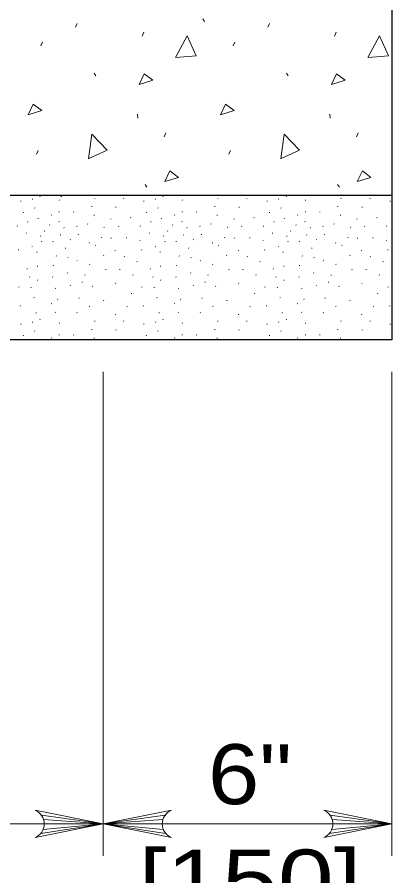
# Model space of a CAD drawing. Extents: x 1083.1 to 1117.1, y 719.4 to 763.4.
# Drawn here: x 1096.472 to 1097.446, y 726.507 to 728.741 of the extents above; entities that cross this region are included whole.
import ezdxf
from ezdxf.enums import TextEntityAlignment as Align

# ---------------------------------------------------------------- set-up
doc = ezdxf.new("R2010")
doc.units = 0
doc.header["$LTSCALE"] = 0.062
doc.layers.add('1', color=7, linetype='Continuous', lineweight=13)

msp = doc.modelspace()

# ---------------------------------------------------------------- linework, layer by layer
at = {"layer": '1'}
for p, q in [((1096.62383, 728.71467), (1096.62825, 728.72467)), ((1096.95492, 728.73642), (1096.95933, 728.72975)), ((1097.12383, 728.71467), (1097.12825, 728.72467)), ((1096.797, 728.6915), (1096.80142, 728.7015)), ((1097.297, 728.6915), (1097.30142, 728.7015)), ((1096.53392, 728.66592), (1096.53833, 728.67592)), ((1097.03392, 728.66592), (1097.03833, 728.67592)), ((1096.67267, 728.59492), (1096.67708, 728.58825)), ((1097.17267, 728.59492), (1097.17708, 728.58825)), ((1096.78483, 728.4885), (1096.786, 728.4785)), ((1097.28483, 728.4885), (1097.286, 728.4785)), ((1096.85408, 728.42958), (1096.8585, 728.43958)), ((1097.35408, 728.42958), (1097.3585, 728.43958)), ((1096.52275, 728.38408), (1096.52725, 728.39408)), ((1097.02275, 728.38408), (1097.02725, 728.39408)), ((1096.80533, 728.30533), (1096.80983, 728.29867)), ((1097.30533, 728.30533), (1097.30983, 728.29867)), ((1096.53142, 728.27367), (1096.532, 728.27533)), ((1096.58583, 728.2755), (1096.5875, 728.27383)), ((1096.85142, 728.27367), (1096.852, 728.27533)), ((1096.95492, 728.27708), (1096.95525, 728.27658)), ((1097.17142, 728.27367), (1097.172, 728.27533)), ((1096.48267, 728.26242), (1096.481, 728.26208)), ((1096.512, 728.26642), (1096.51258, 728.26808)), ((1096.5815, 728.26408), (1096.58208, 728.26575)), ((1096.67383, 728.26875), (1096.67433, 728.27042)), ((1096.749, 728.26875), (1096.74958, 728.27042)), ((1096.80267, 728.26242), (1096.801, 728.26208)), ((1096.832, 728.26642), (1096.83258, 728.26808)), ((1096.9015, 728.26408), (1096.90208, 728.26575)), ((1096.99383, 728.26875), (1096.99433, 728.27042)), ((1097.069, 728.26875), (1097.06958, 728.27042)), ((1097.12267, 728.26242), (1097.121, 728.26208)), ((1097.152, 728.26642), (1097.15258, 728.26808)), ((1097.2215, 728.26408), (1097.22208, 728.26575)), ((1097.31383, 728.26875), (1097.31433, 728.27042)), ((1097.389, 728.26875), (1097.38958, 728.27042)), ((1097.44267, 728.26242), (1097.441, 728.26208)), ((1096.488, 728.23158), (1096.4885, 728.23325)), ((1096.51867, 728.24367), (1096.51783, 728.2445)), ((1096.5825, 728.23458), (1096.58075, 728.23425)), ((1096.61875, 728.23317), (1096.61933, 728.23483)), ((1096.667, 728.2485), (1096.66525, 728.24817)), ((1096.72983, 728.247), (1096.72808, 728.24658)), ((1096.808, 728.23158), (1096.8085, 728.23325)), ((1096.83867, 728.24367), (1096.83783, 728.2445)), ((1096.9025, 728.23458), (1096.90075, 728.23425)), ((1096.93875, 728.23317), (1096.93933, 728.23483)), ((1096.987, 728.2485), (1096.98525, 728.24817)), ((1097.04983, 728.247), (1097.04808, 728.24658)), ((1097.128, 728.23158), (1097.1285, 728.23325)), ((1097.15867, 728.24367), (1097.15783, 728.2445)), ((1097.2225, 728.23458), (1097.22075, 728.23425)), ((1097.25875, 728.23317), (1097.25933, 728.23483)), ((1097.307, 728.2485), (1097.30525, 728.24817)), ((1097.36983, 728.247), (1097.36808, 728.24658)), ((1096.49958, 728.20767), (1096.50017, 728.20933)), ((1096.52675, 728.21642), (1096.52733, 728.21808)), ((1096.56208, 728.22558), (1096.56125, 728.22633)), ((1096.58125, 728.20808), (1096.58042, 728.20892)), ((1096.67317, 728.22608), (1096.6715, 728.22575)), ((1096.71625, 728.21558), (1096.71542, 728.21642)), ((1096.76817, 728.21892), (1096.76733, 728.21975)), ((1096.81958, 728.20767), (1096.82017, 728.20933)), ((1096.84675, 728.21642), (1096.84733, 728.21808)), ((1096.88208, 728.22558), (1096.88125, 728.22633)), ((1096.90125, 728.20808), (1096.90042, 728.20892)), ((1096.99317, 728.22608), (1096.9915, 728.22575)), ((1097.03625, 728.21558), (1097.03542, 728.21642)), ((1097.08817, 728.21892), (1097.08733, 728.21975)), ((1097.13958, 728.20767), (1097.14017, 728.20933)), ((1097.16675, 728.21642), (1097.16733, 728.21808)), ((1097.20208, 728.22558), (1097.20125, 728.22633)), ((1097.22125, 728.20808), (1097.22042, 728.20892)), ((1097.31317, 728.22608), (1097.3115, 728.22575)), ((1097.35625, 728.21558), (1097.35542, 728.21642)), ((1097.40817, 728.21892), (1097.40733, 728.21975)), ((1096.4725, 728.196), (1096.473, 728.19767)), ((1096.55708, 728.19975), (1096.55625, 728.20058)), ((1096.59458, 728.19308), (1096.59375, 728.19392)), ((1096.62792, 728.19642), (1096.62708, 728.19725)), ((1096.65625, 728.20225), (1096.65542, 728.20308)), ((1096.69958, 728.19475), (1096.69792, 728.19392)), ((1096.73625, 728.19642), (1096.73542, 728.19725)), ((1096.7925, 728.196), (1096.793, 728.19767)), ((1096.87708, 728.19975), (1096.87625, 728.20058)), ((1096.91458, 728.19308), (1096.91375, 728.19392)), ((1096.94792, 728.19642), (1096.94708, 728.19725)), ((1096.97625, 728.20225), (1096.97542, 728.20308)), ((1097.01958, 728.19475), (1097.01792, 728.19392)), ((1097.05625, 728.19642), (1097.05542, 728.19725)), ((1097.1125, 728.196), (1097.113, 728.19767)), ((1097.19708, 728.19975), (1097.19625, 728.20058)), ((1097.23458, 728.19308), (1097.23375, 728.19392)), ((1097.26792, 728.19642), (1097.26708, 728.19725)), ((1097.29625, 728.20225), (1097.29542, 728.20308)), ((1097.33958, 728.19475), (1097.33792, 728.19392)), ((1097.37625, 728.19642), (1097.37542, 728.19725)), ((1097.4325, 728.196), (1097.433, 728.19767)), ((1096.49575, 728.178), (1096.49633, 728.17967)), ((1096.533, 728.17033), (1096.5335, 728.172)), ((1096.54308, 728.18475), (1096.54375, 728.18442)), ((1096.54375, 728.18442), (1096.54408, 728.184)), ((1096.58467, 728.17342), (1096.58525, 728.17508)), ((1096.63117, 728.17492), (1096.63175, 728.17658)), ((1096.69167, 728.16717), (1096.69225, 728.16883)), ((1096.7165, 728.16542), (1096.717, 728.16708)), ((1096.75775, 728.16683), (1096.756, 728.16642)), ((1096.81575, 728.178), (1096.81633, 728.17967)), ((1096.853, 728.17033), (1096.8535, 728.172)), ((1096.86308, 728.18475), (1096.86375, 728.18442)), ((1096.86375, 728.18442), (1096.86408, 728.184)), ((1096.90467, 728.17342), (1096.90525, 728.17508)), ((1096.95117, 728.17492), (1096.95175, 728.17658)), ((1097.01167, 728.16717), (1097.01225, 728.16883)), ((1097.0365, 728.16542), (1097.037, 728.16708)), ((1097.07775, 728.16683), (1097.076, 728.16642)), ((1097.13575, 728.178), (1097.13633, 728.17967)), ((1097.173, 728.17033), (1097.1735, 728.172)), ((1097.18308, 728.18475), (1097.18375, 728.18442)), ((1097.18375, 728.18442), (1097.18408, 728.184)), ((1097.22467, 728.17342), (1097.22525, 728.17508)), ((1097.27117, 728.17492), (1097.27175, 728.17658)), ((1097.33167, 728.16717), (1097.33225, 728.16883)), ((1097.3565, 728.16542), (1097.357, 728.16708)), ((1097.39775, 728.16683), (1097.396, 728.16642)), ((1096.51125, 728.143), (1096.51183, 728.14458)), ((1096.53608, 728.15633), (1096.53667, 728.158)), ((1096.56525, 728.15608), (1096.56583, 728.15775)), ((1096.61075, 728.162), (1096.60992, 728.16283)), ((1096.65983, 728.153), (1096.66042, 728.15467)), ((1096.67667, 728.1465), (1096.67583, 728.14733)), ((1096.79217, 728.15967), (1096.79133, 728.1605)), ((1096.83125, 728.143), (1096.83183, 728.14458)), ((1096.85608, 728.15633), (1096.85667, 728.158)), ((1096.88525, 728.15608), (1096.88583, 728.15775)), ((1096.93075, 728.162), (1096.92992, 728.16283)), ((1096.97983, 728.153), (1096.98042, 728.15467)), ((1096.99667, 728.1465), (1096.99583, 728.14733)), ((1097.11217, 728.15967), (1097.11133, 728.1605)), ((1097.15125, 728.143), (1097.15183, 728.14458)), ((1097.17608, 728.15633), (1097.17667, 728.158)), ((1097.20525, 728.15608), (1097.20583, 728.15775)), ((1097.25075, 728.162), (1097.24992, 728.16283)), ((1097.29983, 728.153), (1097.30042, 728.15467)), ((1097.31667, 728.1465), (1097.31583, 728.14733)), ((1097.43217, 728.15967), (1097.43133, 728.1605)), ((1096.47558, 728.13442), (1096.47617, 728.13608)), ((1096.52458, 728.12967), (1096.52283, 728.12933)), ((1096.57425, 728.11942), (1096.57342, 728.12025)), ((1096.59783, 728.13908), (1096.59842, 728.14075)), ((1096.69758, 728.121), (1096.69675, 728.12183)), ((1096.72825, 728.13358), (1096.7265, 728.13317)), ((1096.79558, 728.13442), (1096.79617, 728.13608)), ((1096.84458, 728.12967), (1096.84283, 728.12933)), ((1096.89425, 728.11942), (1096.89342, 728.12025)), ((1096.91783, 728.13908), (1096.91842, 728.14075)), ((1097.01758, 728.121), (1097.01675, 728.12183)), ((1097.04825, 728.13358), (1097.0465, 728.13317)), ((1097.11558, 728.13442), (1097.11617, 728.13608)), ((1097.16458, 728.12967), (1097.16283, 728.12933)), ((1097.21425, 728.11942), (1097.21342, 728.12025)), ((1097.23783, 728.13908), (1097.23842, 728.14075)), ((1097.33758, 728.121), (1097.33675, 728.12183)), ((1097.36825, 728.13358), (1097.3665, 728.13317)), ((1097.43558, 728.13442), (1097.43617, 728.13608)), ((1096.6045, 728.11475), (1096.60367, 728.11558)), ((1096.62808, 728.10658), (1096.62858, 728.10825)), ((1096.66108, 728.09775), (1096.66025, 728.09858)), ((1096.75108, 728.11708), (1096.75025, 728.11792)), ((1096.78483, 728.10492), (1096.78317, 728.10458)), ((1096.9245, 728.11475), (1096.92367, 728.11558)), ((1096.94808, 728.10658), (1096.94858, 728.10825)), ((1096.98108, 728.09775), (1096.98025, 728.09858)), ((1097.07108, 728.11708), (1097.07025, 728.11792)), ((1097.10483, 728.10492), (1097.10317, 728.10458)), ((1097.2445, 728.11475), (1097.24367, 728.11558)), ((1097.26808, 728.10658), (1097.26858, 728.10825)), ((1097.30108, 728.09775), (1097.30025, 728.09858)), ((1097.39108, 728.11708), (1097.39025, 728.11792)), ((1097.42483, 728.10492), (1097.42317, 728.10458)), ((1096.49808, 728.08567), (1096.49858, 728.08733)), ((1096.52617, 728.09333), (1096.52442, 728.09292)), ((1096.566, 728.09425), (1096.56658, 728.09592)), ((1096.60375, 728.07458), (1096.60292, 728.07542)), ((1096.7025, 728.08342), (1096.70308, 728.08508)), ((1096.73992, 728.08483), (1096.73817, 728.08442)), ((1096.81808, 728.08567), (1096.81858, 728.08733)), ((1096.84617, 728.09333), (1096.84442, 728.09292)), ((1096.886, 728.09425), (1096.88658, 728.09592)), ((1096.92375, 728.07458), (1096.92292, 728.07542)), ((1097.0225, 728.08342), (1097.02308, 728.08508)), ((1097.05992, 728.08483), (1097.05817, 728.08442)), ((1097.13808, 728.08567), (1097.13858, 728.08733)), ((1097.16617, 728.09333), (1097.16442, 728.09292)), ((1097.206, 728.09425), (1097.20658, 728.09592)), ((1097.24375, 728.07458), (1097.24292, 728.07542)), ((1097.3425, 728.08342), (1097.34308, 728.08508)), ((1097.37992, 728.08483), (1097.37817, 728.08442)), ((1096.5055, 728.0645), (1096.50467, 728.06533)), ((1096.52525, 728.05575), (1096.52575, 728.05742)), ((1096.56542, 728.06433), (1096.56458, 728.06517)), ((1096.64217, 728.05158), (1096.6405, 728.05117)), ((1096.64825, 728.06867), (1096.64875, 728.07033)), ((1096.77308, 728.06942), (1096.77367, 728.07108)), ((1096.8255, 728.0645), (1096.82467, 728.06533)), ((1096.84525, 728.05575), (1096.84575, 728.05742)), ((1096.88542, 728.06433), (1096.88458, 728.06517)), ((1096.96217, 728.05158), (1096.9605, 728.05117)), ((1096.96825, 728.06867), (1096.96875, 728.07033)), ((1097.09308, 728.06942), (1097.09367, 728.07108)), ((1097.1455, 728.0645), (1097.14467, 728.06533)), ((1097.16525, 728.05575), (1097.16575, 728.05742)), ((1097.20542, 728.06433), (1097.20458, 728.06517)), ((1097.28217, 728.05158), (1097.2805, 728.05117)), ((1097.28825, 728.06867), (1097.28875, 728.07033)), ((1097.41308, 728.06942), (1097.41367, 728.07108)), ((1096.47725, 728.03917), (1096.47558, 728.03883)), ((1096.50817, 728.037), (1096.50867, 728.03867)), ((1096.57292, 728.03608), (1096.57125, 728.03525)), ((1096.61075, 728.04283), (1096.60992, 728.04367)), ((1096.66883, 728.0405), (1096.668, 728.04133)), ((1096.72858, 728.04825), (1096.72775, 728.04908)), ((1096.79725, 728.03917), (1096.79558, 728.03883)), ((1096.82817, 728.037), (1096.82867, 728.03867)), ((1096.89292, 728.03608), (1096.89125, 728.03525)), ((1096.93075, 728.04283), (1096.92992, 728.04367)), ((1096.98883, 728.0405), (1096.988, 728.04133)), ((1097.04858, 728.04825), (1097.04775, 728.04908)), ((1097.11725, 728.03917), (1097.11558, 728.03883)), ((1097.14817, 728.037), (1097.14867, 728.03867)), ((1097.21292, 728.03608), (1097.21125, 728.03525)), ((1097.25075, 728.04283), (1097.24992, 728.04367)), ((1097.30883, 728.0405), (1097.308, 728.04133)), ((1097.36858, 728.04825), (1097.36775, 728.04908)), ((1097.43725, 728.03917), (1097.43558, 728.03883)), ((1096.51633, 728.01033), (1096.5155, 728.01117)), ((1096.57792, 728.00617), (1096.57708, 728.007)), ((1096.63275, 728.00908), (1096.63325, 728.01075)), ((1096.76917, 728.0215), (1096.76975, 728.02317)), ((1096.83633, 728.01033), (1096.8355, 728.01117)), ((1096.89792, 728.00617), (1096.89708, 728.007)), ((1096.95275, 728.00908), (1096.95325, 728.01075)), ((1097.08917, 728.0215), (1097.08975, 728.02317)), ((1097.15633, 728.01033), (1097.1555, 728.01117)), ((1097.21792, 728.00617), (1097.21708, 728.007)), ((1097.27275, 728.00908), (1097.27325, 728.01075)), ((1097.40917, 728.0215), (1097.40975, 728.02317)), ((1096.48025, 727.989), (1096.48075, 727.99067)), ((1096.56208, 727.99617), (1096.56042, 727.99533)), ((1096.66158, 727.98892), (1096.65983, 727.9885)), ((1096.69708, 728.00292), (1096.69767, 728.00458)), ((1096.75808, 727.98708), (1096.75725, 727.98792)), ((1096.80025, 727.989), (1096.80075, 727.99067)), ((1096.88208, 727.99617), (1096.88042, 727.99533)), ((1096.98158, 727.98892), (1096.97983, 727.9885)), ((1097.01708, 728.00292), (1097.01767, 728.00458)), ((1097.07808, 727.98708), (1097.07725, 727.98792)), ((1097.12025, 727.989), (1097.12075, 727.99067)), ((1097.20208, 727.99617), (1097.20042, 727.99533)), ((1097.30158, 727.98892), (1097.29983, 727.9885)), ((1097.33708, 728.00292), (1097.33767, 728.00458)), ((1097.39808, 727.98708), (1097.39725, 727.98792)), ((1097.44025, 727.989), (1097.44075, 727.99067)), ((1096.52225, 727.97183), (1096.5205, 727.9715)), ((1096.57208, 727.97292), (1096.57125, 727.97375)), ((1096.62858, 727.97175), (1096.62775, 727.9725)), ((1096.72733, 727.96667), (1096.72792, 727.96833)), ((1096.84225, 727.97183), (1096.8405, 727.9715)), ((1096.89208, 727.97292), (1096.89125, 727.97375)), ((1096.94858, 727.97175), (1096.94775, 727.9725)), ((1097.04733, 727.96667), (1097.04792, 727.96833)), ((1097.16225, 727.97183), (1097.1605, 727.9715)), ((1097.21208, 727.97292), (1097.21125, 727.97375)), ((1097.26858, 727.97175), (1097.26775, 727.9725)), ((1097.36733, 727.96667), (1097.36792, 727.96833)), ((1096.48267, 727.9425), (1096.481, 727.94217)), ((1096.512, 727.9465), (1096.51258, 727.94817)), ((1096.53142, 727.95375), (1096.532, 727.95542)), ((1096.5815, 727.94417), (1096.58208, 727.94583)), ((1096.67383, 727.94883), (1096.67433, 727.9505)), ((1096.749, 727.94883), (1096.74958, 727.9505)), ((1096.80267, 727.9425), (1096.801, 727.94217)), ((1096.832, 727.9465), (1096.83258, 727.94817)), ((1096.85142, 727.95375), (1096.852, 727.95542)), ((1096.9015, 727.94417), (1096.90208, 727.94583)), ((1096.99383, 727.94883), (1096.99433, 727.9505)), ((1097.069, 727.94883), (1097.06958, 727.9505)), ((1097.12267, 727.9425), (1097.121, 727.94217)), ((1097.152, 727.9465), (1097.15258, 727.94817)), ((1097.17142, 727.95375), (1097.172, 727.95542)), ((1097.2215, 727.94417), (1097.22208, 727.94583)), ((1097.31383, 727.94883), (1097.31433, 727.9505)), ((1097.389, 727.94883), (1097.38958, 727.9505)), ((1097.44267, 727.9425), (1097.441, 727.94217)), ((1096.51867, 727.92375), (1096.51783, 727.92458)), ((1096.667, 727.92858), (1096.66525, 727.92825)), ((1096.72983, 727.92708), (1096.72808, 727.92667)), ((1096.83867, 727.92375), (1096.83783, 727.92458)), ((1096.987, 727.92858), (1096.98525, 727.92825)), ((1097.04983, 727.92708), (1097.04808, 727.92667)), ((1097.15867, 727.92375), (1097.15783, 727.92458)), ((1097.307, 727.92858), (1097.30525, 727.92825)), ((1097.36983, 727.92708), (1097.36808, 727.92667)), ((1096.488, 727.91167), (1096.4885, 727.91333)), ((1096.56208, 727.90567), (1096.56125, 727.90642)), ((1096.5825, 727.91467), (1096.58075, 727.91433)), ((1096.61875, 727.91325), (1096.61933, 727.91492)), ((1096.67317, 727.90617), (1096.6715, 727.90583)), ((1096.808, 727.91167), (1096.8085, 727.91333)), ((1096.88208, 727.90567), (1096.88125, 727.90642)), ((1096.9025, 727.91467), (1096.90075, 727.91433)), ((1096.93875, 727.91325), (1096.93933, 727.91492)), ((1096.99317, 727.90617), (1096.9915, 727.90583)), ((1097.128, 727.91167), (1097.1285, 727.91333)), ((1097.20208, 727.90567), (1097.20125, 727.90642)), ((1097.2225, 727.91467), (1097.22075, 727.91433)), ((1097.25875, 727.91325), (1097.25933, 727.91492)), ((1097.31317, 727.90617), (1097.3115, 727.90583)), ((1096.69608, 727.81825), (1096.69608, 726.55892)), ((1097.44608, 727.81825), (1097.44608, 726.55892)), ((1096.53583, 726.66467), (1096.69608, 726.64225)), ((1096.54125, 726.65358), (1096.69608, 726.64225)), ((1096.85642, 726.66467), (1096.69608, 726.64225)), ((1096.851, 726.65358), (1096.69608, 726.64225)), ((1097.28575, 726.66467), (1097.44608, 726.64225)), ((1097.29117, 726.65358), (1097.44608, 726.64225)), ((1096.69617, 726.64225), (1094.55033, 726.64225)), ((1096.53392, 726.6175), (1096.69608, 726.64225)), ((1096.54008, 726.62783), (1096.69608, 726.64225)), ((1096.54292, 726.64225), (1096.69608, 726.64225)), ((1096.69608, 726.64225), (1097.44608, 726.64225)), ((1096.84933, 726.64225), (1096.69608, 726.64225)), ((1096.85217, 726.62783), (1096.69608, 726.64225)), ((1096.85833, 726.6175), (1096.69608, 726.64225)), ((1097.28383, 726.6175), (1097.44608, 726.64225)), ((1097.29, 726.62783), (1097.44608, 726.64225)), ((1097.29283, 726.64225), (1097.44608, 726.64225))]:
    msp.add_line(p, q, dxfattribs=at)
at = {"layer": '1', "lineweight": 25}
for p, q in [((1097.44608, 728.27658), (1094.44633, 728.27658)), ((1097.44608, 727.90158), (1094.44633, 727.90158))]:
    msp.add_line(p, q, dxfattribs=at)
msp.add_lwpolyline([(1097.44608, 733.17933), (1097.44608, 729.87108), (1097.44608, 727.90158)], dxfattribs=at)
at = {"layer": '1'}
for points in [[(1096.884, 728.636), (1096.914, 728.69258), (1096.93733, 728.64042), (1096.88517, 728.636)], [(1097.384, 728.636), (1097.414, 728.69258), (1097.43733, 728.64042), (1097.38517, 728.636)], [(1096.65783, 728.37258), (1096.66667, 728.43608), (1096.70642, 728.395), (1096.65883, 728.373)], [(1097.15783, 728.37258), (1097.16667, 728.43608), (1097.20642, 728.395), (1097.15883, 728.373)], [(1096.519, 726.60683), (1096.69608, 726.64225), (1096.519, 726.67767)], [(1096.87317, 726.60683), (1096.69608, 726.64225), (1096.87317, 726.67767)], [(1097.269, 726.60683), (1097.44608, 726.64225), (1097.269, 726.67767)]]:
    msp.add_lwpolyline(points, dxfattribs=at)
for points in [[(1096.78917, 728.56608), (1096.8025, 728.59383), (1096.82475, 728.57717)], [(1097.28917, 728.56608), (1097.3025, 728.59383), (1097.32475, 728.57717)], [(1096.50083, 728.48675), (1096.51417, 728.5145), (1096.53633, 728.49792)], [(1097.00083, 728.48675), (1097.01417, 728.5145), (1097.03633, 728.49792)], [(1096.85625, 728.31308), (1096.86958, 728.34083), (1096.89183, 728.32417)], [(1097.35625, 728.31308), (1097.36958, 728.34083), (1097.39183, 728.32417)]]:
    msp.add_lwpolyline(points, close=True, dxfattribs=at)
for centre, start, end in [((1096.50473, 726.64231), 292.08605, 67.91218), ((1096.88748, 726.64231), 112.08782, 247.91395), ((1097.25469, 726.64231), 292.08605, 67.91218)]:
    msp.add_arc(centre, 0.03822, start, end, dxfattribs=at)

# ---------------------------------------------------------------- texts
for s, width, p in [('6"', 1.15, (1097.07758, 726.69358)), ('[150]', 1.25, (1097.07758, 726.4195))]:
    msp.add_text(s, height=0.156, dxfattribs=dict(at, width=width)).set_placement(p, align=Align.CENTER)

doc.saveas('drawing.dxf')
